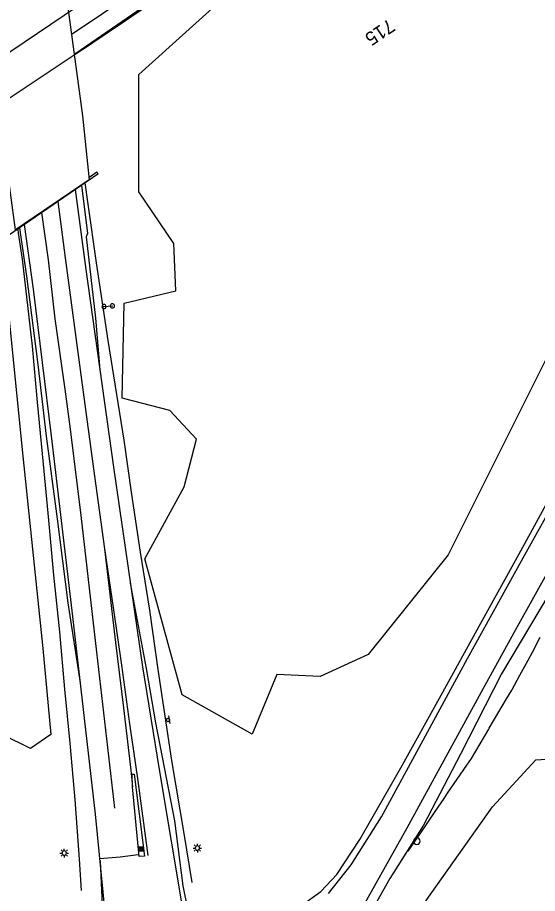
# Model space of a CAD drawing. Extents: x 1901471 to 1963503, y 756461 to 799997.
# Drawn here: x 1912024 to 1912329, y 761265 to 761779 of the extents above; entities that cross this region are included whole.
import ezdxf

# ---------------------------------------------------------------- set-up
doc = ezdxf.new("R2010")
doc.units = 0
for name, color, linetype in [('Default', 7, 'Continuous'), ('RD_DTM_BkLn1', 7, 'Continuous'), ('RD_EX_Bldg', 7, 'Continuous'), ('RD_EX_BldgApp', 7, 'Continuous'), ('RD_EX_Bridge', 7, 'Continuous'), ('RD_EX_DR_Inlet', 7, 'Continuous'), ('RD_EX_GuardRail', 7, 'Continuous'), ('RD_EX_Road', 7, 'Continuous'), ('RD_EX_UT', 7, 'Continuous'), ('RD_EX_VEG', 7, 'Continuous'), ('RD_HC_Cl', 7, 'Continuous'), ('RD_HC_TX_Sta50', 7, 'Continuous')]:
    doc.layers.add(name, color=color, linetype=linetype)

# ---------------------------------------------------------------- blocks, each defined once
blk = doc.blocks.new('TSP')
at = {"layer": 'Default'}
for points in [[(-0.127, 0), (-0.0635, 0)], [(-0.0635, 0.0635), (-0.09525, 0.09525)], [(0, 0.0635), (0, 0.127)], [(0.0635, 0.0635), (0.09525, 0.09525)], [(0.0635, 0), (0.127, 0)], [(-0.0635, -0.0635), (-0.09525, -0.09525)], [(0, -0.0635), (0, -0.127)], [(0.0635, -0.0635), (0.09525, -0.09525)]]:
    blk.add_lwpolyline(points, dxfattribs=at)
for start, end in [(0, 180), (180, 0)]:
    blk.add_arc((0, 0), 0.0635, start, end, dxfattribs=at)
blk = doc.blocks.new('OP')
at = {"layer": 'Default'}
for start, end in [(90, 270), (270, 90)]:
    blk.add_arc((0, 0), 0.127, start, end, dxfattribs=at)
blk = doc.blocks.new('SIGN')
at = {"layer": 'RD_EX_BldgApp'}
blk.add_line((-4.5, -2), (4.5, -2), dxfattribs=at)
blk.add_circle((0, 0), 2, dxfattribs=at)
blk = doc.blocks.new('SIGNPOST')
at = {"layer": 'Default'}
for start, end in [(90, 270), (270, 90)]:
    blk.add_arc((0, 0), 0.127, start, end, dxfattribs=at)
blk = doc.blocks.new('DI')
at = {"layer": 'RD_EX_DR_Inlet'}
for p, q in [((-2.5, 0.9), (2.5, 0.9)), ((-0.8, 2.6), (-0.8, -2.4)), ((0.9, 2.6), (0.9, -2.4)), ((-2.5, -0.8), (2.5, -0.8))]:
    blk.add_line(p, q, dxfattribs=at)
blk.add_lwpolyline([(-2.5, -2.4), (-2.5, 2.6), (2.5, 2.6), (2.5, -2.4)], close=True, dxfattribs=at)

msp = doc.modelspace()

# ---------------------------------------------------------------- linework, layer by layer
at = {"layer": 'RD_DTM_BkLn1'}
for points in [[(1912007.71, 761724.77), (1912057.71, 761757.92), (1912066.04, 761763.45), (1912068.12, 761764.82), (1912076.4, 761770.42), (1912084.69, 761776.02), (1912092.97, 761781.61), (1912101.26, 761787.21), (1912102.61, 761788.12), (1912110.91, 761793.69), (1912119.22, 761799.25), (1912127.53, 761804.81), (1912135.78, 761810.34), (1912144.02, 761816.01), (1912152.26, 761821.68), (1912160.5, 761827.35), (1912168.78, 761833.05), (1912177.08, 761838.63), (1912185.37, 761844.22), (1912193.67, 761849.8), (1912201.96, 761855.39), (1912210.26, 761860.97), (1912211.78, 761861.99)], [(1912253.09, 761290.2), (1912258.71, 761298.47), (1912262.91, 761304.66), (1912268.52, 761312.93), (1912274.13, 761321.21), (1912276.17, 761324.22), (1912281.82, 761332.47), (1912287.48, 761340.71), (1912290.11, 761344.55), (1912295.2, 761353.16), (1912300.28, 761361.77), (1912300.62, 761362.35), (1912305.68, 761370.97), (1912310.74, 761379.6), (1912313.77, 761384.77), (1912318.58, 761393.53), (1912323.39, 761402.3), (1912325.95, 761406.96), (1912330.55, 761415.83)]]:
    msp.add_lwpolyline(points, dxfattribs=at)
at = {"layer": 'RD_EX_Bldg'}
for points in [[(1912065.74, 761685.66), (1912070.4, 761688.88), (1912070.91, 761687.61), (1912018.63, 761651.52)], [(1912074.28, 761609.88), (1912079.73, 761610.24)]]:
    msp.add_lwpolyline(points, dxfattribs=at)
at = {"layer": 'RD_EX_Bridge'}
msp.add_lwpolyline([(1911982.87, 761953.96), (1912027.01, 761985.15), (1912046.45, 761837.59), (1912062.04, 761721.82), (1912065.88, 761684.27), (1912022.71, 761654.96), (1912003.98, 761792.72), (1911987.67, 761919.89)], close=True, dxfattribs=at)
at = {"layer": 'RD_EX_GuardRail'}
for points in [[(1912126.28, 761271.85), (1912121.69, 761300.67), (1912114.43, 761343.45), (1912106.39, 761396.81), (1912101.42, 761431.62), (1912096.06, 761465.73), (1912090.96, 761499.58), (1912086.37, 761531.4), (1912077.07, 761589.92), (1912070.18, 761635.51), (1912065.33, 761669.87), (1912063.55, 761682.53)], [(1912023.99, 761655.22), (1912024.28, 761652.98), (1912026.7, 761637.74), (1912032.44, 761586.67), (1912035.5, 761553.84), (1912038.94, 761517.43), (1912042, 761484.6), (1912045.06, 761452.28), (1912048.5, 761418.93), (1912051.44, 761385.33), (1912054.5, 761353.65), (1912057.43, 761320.43), (1912060.11, 761285.56), (1912061.25, 761267.13)]]:
    msp.add_lwpolyline(points, dxfattribs=at)
at = {"layer": 'RD_EX_Road'}
for points in [[(1912176.8, 761840.32), (1912061.18, 761760.45), (1912057.19, 761757.84)], [(1912554.01, 761839.1), (1912516.14, 761769.97), (1912477.28, 761699.34), (1912440.41, 761631.95), (1912408.77, 761574.28), (1912378.62, 761519.6), (1912335.78, 761441.25), (1912307.87, 761394.29), (1912283.71, 761347.2), (1912262.03, 761305.6), (1912242.35, 761274.21), (1912200.5, 761199.84)], [(1912143.4, 761828.57), (1912060.05, 761772.53), (1912055.62, 761769.53)], [(1912536.18, 761819.2), (1912511.15, 761773.7), (1912489.75, 761734.74), (1912467.39, 761694.52), (1912444.25, 761653.04), (1912423.31, 761615.18), (1912398.13, 761568.98), (1912359.72, 761499.87), (1912336.1, 761456.35), (1912315.95, 761420.06), (1912295.8, 761383.62), (1912275.18, 761345.6), (1912252.2, 761303.81), (1912224.02, 761253.51)], [(1912206.24, 761265.4), (1912219.63, 761282.24), (1912237.33, 761310.42), (1912252.02, 761337.42), (1912287.86, 761403.28), (1912320.47, 761462.34), (1912382.01, 761572.9), (1912413.54, 761630.45), (1912454.57, 761704.84), (1912505.74, 761796.83)], [(1912189.86, 761258), (1912201.83, 761266.66), (1912211.11, 761276.57), (1912224.65, 761297.19), (1912248.74, 761339.15), (1912272.35, 761381.89), (1912295.65, 761424), (1912319.1, 761466.58), (1912339.88, 761504.44), (1912361.61, 761544.03), (1912385.38, 761587.4), (1912409.3, 761631.08), (1912425.05, 761658.86), (1912447.56, 761700.03), (1912470.54, 761742.3), (1912491.63, 761779.84)], [(1912057.76, 761678.53), (1912063.93, 761631.52), (1912080.13, 761515.57), (1912097.19, 761398.53), (1912106.91, 761338.17), (1912121.16, 761252.88)], [(1912061.36, 761681.02), (1912064.98, 761652.77), (1912064.07, 761650.86), (1912069.72, 761602.95), (1912072.15, 761572.68)], [(1912047.61, 761671.52), (1912051.92, 761638.51), (1912061.35, 761566.85), (1912069.13, 761510.24), (1912075, 761467.59), (1912081.37, 761412.63), (1912085.96, 761374.44), (1912090.43, 761337.78), (1912091.3, 761327.96)], [(1912080.99, 761315.41), (1912070.46, 761407.07), (1912061.17, 761487.27), (1912054.98, 761537.97), (1912051.79, 761561.37), (1912046.05, 761602.75), (1912041.97, 761637.36), (1912038.1, 761664.96)], [(1911998.94, 761210.45), (1912025.07, 761212.82), (1912041.26, 761215.2), (1912055.51, 761218.65), (1912061.99, 761221.67), (1912072.14, 761230.31), (1912076.03, 761235.49), (1912076.46, 761242.4), (1912069.55, 761311.94), (1912056.38, 761427.89), (1912043.85, 761533.92), (1912033.27, 761619.97), (1912027.96, 761657.96)], [(1912060.78, 761389.09), (1912053.69, 761436), (1912047.28, 761485.21), (1912040.87, 761533.82), (1912035.99, 761575.86), (1912029.43, 761627.67), (1912025.46, 761654.6), (1912025.26, 761656.1)], [(1912075, 761467.59), (1912080.23, 761431.88), (1912084.82, 761399.37), (1912089.66, 761365), (1912094.25, 761332.81), (1912100.37, 761287.8)], [(1912090.04, 761447.55), (1912099.35, 761397.52), (1912104.83, 761365.51), (1912108.82, 761345.46), (1912116.05, 761308.09), (1912120.78, 761269.97), (1912123.5, 761256.37)], [(1912072.14, 761285.91), (1912084.05, 761286.89), (1912094.6, 761288.3)], [(1912072.27, 761284.55), (1912073.94, 761249.92), (1912071.95, 761235.72), (1912064.97, 761228.49), (1912046.04, 761220.52), (1911959.1, 761211.3), (1911898.88, 761205.6)]]:
    msp.add_lwpolyline(points, dxfattribs=at)
msp.add_lwpolyline([(1912095.25, 761287.16), (1912091.3, 761327.96), (1912091.17, 761335.36), (1912092.32, 761335.49), (1912098.44, 761287.29)], close=True, dxfattribs=at)
at = {"layer": 'RD_EX_VEG'}
msp.add_lwpolyline([(1912382.97, 761792.11), (1912404.75, 761757.02), (1912399.91, 761729.19), (1912368.45, 761732.82), (1912361.19, 761691.68), (1912378.13, 761654.17), (1912341.83, 761594.88), (1912276.49, 761464.21), (1912229.51, 761405.67), (1912201.47, 761392.82), (1912176.06, 761394.03), (1912161.54, 761358.94), (1912120.4, 761381.93), (1912098.62, 761461.79), (1912121.61, 761504.14), (1912128.87, 761531.96), (1912113.14, 761548.9), (1912085.31, 761556.16), (1912086.52, 761611.82), (1912116.77, 761619.08), (1912115.56, 761646.91), (1912094.99, 761677.16), (1912094.99, 761746.13), (1912157.91, 761803)], dxfattribs=at)
for points in [[(1912015.99, 761631.44), (1912027, 761522.09), (1912038.77, 761409.12), (1912043.33, 761358.81), (1912031.56, 761350.46), (1912015.23, 761358.43), (1912016.75, 761392.23), (1912008.78, 761449.94), (1912004.22, 761491.71), (1912002.7, 761557.21), (1911993.21, 761604.86), (1911989.41, 761629.16), (1911993.97, 761639.8), (1912007.26, 761639.8), (1912012.95, 761638.28)], [(1912299.25, 761174.14), (1912282.85, 761181.64), (1912280.5, 761209.77), (1912259.41, 761223.83), (1912263.63, 761261.33), (1912302.54, 761316.18), (1912327.85, 761343.84), (1912349.88, 761345.24), (1912366.29, 761364.93), (1912389.26, 761369.62), (1912395.82, 761348.53), (1912361.13, 761281.96), (1912328.32, 761225.71), (1912318.94, 761197.11)]]:
    msp.add_lwpolyline(points, close=True, dxfattribs=at)
at = {"layer": 'RD_HC_Cl'}
msp.add_line((1916195.77, 764578.09), (1911854.45, 761647.95), dxfattribs=at)

# ---------------------------------------------------------------- block references
at = {"layer": 'RD_EX_Bldg', "xscale": 9.84251968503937, "yscale": 9.84251968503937}
for p in [(1912079.57, 761610.28), (1912074.61, 761609.89)]:
    msp.add_blockref('SIGNPOST', p, dxfattribs=at)
at = {"layer": 'RD_EX_Bldg', "xscale": 0.5039370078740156, "yscale": 0.5039370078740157, "rotation": 99.09027700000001}
msp.add_blockref('SIGN', (1912112.1, 761367.24), dxfattribs=at)
at = {"layer": 'RD_EX_DR_Inlet', "xscale": 0.5039370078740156, "yscale": 0.5039370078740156}
msp.add_blockref('DI', (1912096.27, 761291.49), dxfattribs=at)
at = {"layer": 'RD_EX_UT'}
for name, p, xscale, yscale in [('OP', (1912258.12, 761296.15), 15.748031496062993, 15.748031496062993), ('TSP', (1912129.39, 761292.06), 19.68503937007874, 19.68503937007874), ('TSP', (1912051.28, 761289.13), 19.68503937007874, 19.68503937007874)]:
    msp.add_blockref(name, p, dxfattribs=dict(at, xscale=xscale, yscale=yscale))

# ---------------------------------------------------------------- texts
at = {"layer": 'RD_HC_TX_Sta50'}
msp.add_text('715', height=8, rotation=214.0171, dxfattribs=at).set_placement((1912241.72, 761779.03))

doc.saveas('drawing.dxf')
